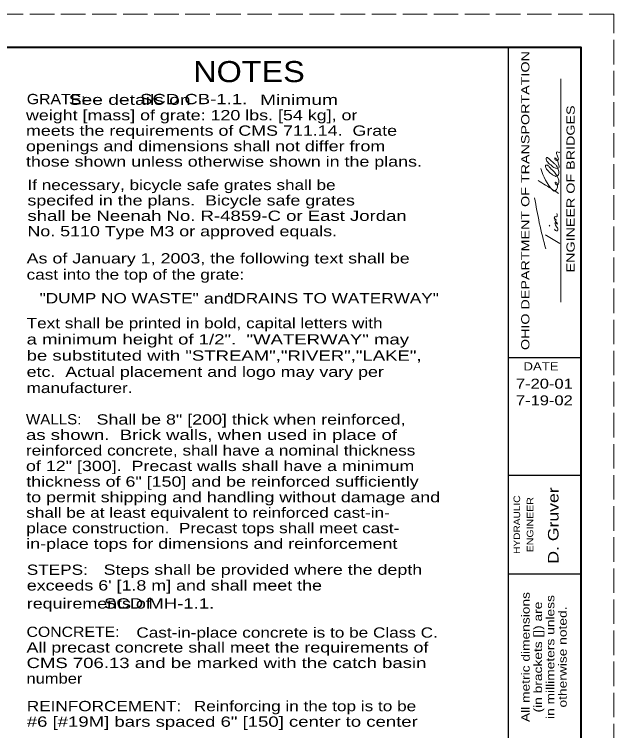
# Model space of a CAD drawing. Extents: x 1329.9 to 1363.9, y 715.5 to 737.5.
# Drawn here: x 1354.76 to 1363.86, y 726.62 to 737.5 of the extents above; entities that cross this region are included whole.
import ezdxf
from ezdxf.enums import TextEntityAlignment as Align

# ---------------------------------------------------------------- set-up
doc = ezdxf.new("R2010")
doc.units = 0
doc.header["$LTSCALE"] = 0.062
doc.linetypes.add('LONG_DASHED', pattern=[7.5, 6, -1.5])
doc.layers.add('1', color=7, linetype='Continuous', lineweight=13)

msp = doc.modelspace()

# ---------------------------------------------------------------- linework, layer by layer
at = {"layer": '1', "lineweight": 25}
for p, q in [((1331.86333, 736.9975), (1363.36333, 736.9975)), ((1362.26333, 715.9975), (1362.26333, 736.9975)), ((1363.36333, 736.9975), (1363.36333, 715.9975)), ((1363.36333, 732.28167), (1362.26333, 732.28167)), ((1363.36333, 730.4975), (1362.26333, 730.4975)), ((1363.36333, 728.9975), (1362.26333, 728.9975))]:
    msp.add_line(p, q, dxfattribs=at)
at = {"layer": '1'}
for p, q in [((1363.06208, 733.1285), (1363.06208, 736.51858)), ((1362.89458, 734.27942), (1362.88442, 734.29867))]:
    msp.add_line(p, q, dxfattribs=at)
at = {"layer": '1', "linetype": 'LONG_DASHED'}
msp.add_lwpolyline([(1329.86333, 715.4975), (1363.86333, 715.4975), (1363.86333, 737.4975), (1329.86333, 737.4975)], close=True, dxfattribs=at)
at = {"layer": '1', "lineweight": 40}
msp.add_lwpolyline([(1331.86333, 736.9975), (1363.36333, 736.9975), (1363.36333, 715.9975), (1331.86333, 715.9975)], close=True, dxfattribs=at)
msp.add_lwpolyline([(1331.86333, 736.9975), (1363.36333, 736.9975), (1363.36333, 715.9975), (1331.86333, 715.9975)], close=True, dxfattribs=at)
at = {"layer": '1'}
for points in [[(1362.75517, 735.1545), (1362.93833, 734.82617), (1362.9535, 734.81558), (1362.96367, 734.81558), (1362.99558, 734.83925), (1363.01067, 734.87342), (1363.00567, 734.92467), (1362.98875, 734.9465), (1362.97525, 734.9465), (1362.9735, 734.9335), (1362.98367, 734.91833), (1362.99717, 734.90992), (1363.01225, 734.90992), (1363.02742, 734.9315), (1363.03083, 734.95083), (1363.02058, 735.00617), (1362.93833, 735.12658), (1362.89283, 735.17125), (1362.85592, 735.20583), (1362.83075, 735.208), (1362.8325, 735.16942), (1362.85767, 735.13067), (1362.92492, 735.06833), (1362.967, 735.04292), (1363.00067, 735.03842), (1363.024, 735.06442), (1363.03083, 735.09858), (1363.02575, 735.12433), (1362.99558, 735.1975), (1362.96533, 735.2295), (1362.90475, 735.28292), (1362.87608, 735.30875), (1362.84258, 735.324), (1362.83917, 735.296), (1362.84925, 735.27017), (1362.90642, 735.21025), (1362.97708, 735.163), (1363.02908, 735.16533), (1363.02742, 735.223), (1363.01558, 735.26592), (1363.00225, 735.29167), (1362.99208, 735.30242), (1362.96867, 735.31742), (1362.97042, 735.30033), (1363.00567, 735.27883), (1363.02058, 735.28958), (1363.0075, 735.34325), (1362.99892, 735.37117), (1362.99558, 735.38383), (1362.99558, 735.39667), (1362.99558, 735.40533), (1363.02058, 735.40317), (1363.046, 735.40317)], [(1362.71633, 734.97225), (1362.94008, 734.83475), (1363.02575, 734.77908)], [(1362.83258, 733.93525), (1362.73392, 734.3305), (1362.66267, 734.71283)], [(1362.96367, 734.23417), (1362.97192, 734.2235), (1363.00908, 734.21058), (1363.01383, 734.243), (1362.98875, 734.27942), (1362.9735, 734.31567), (1362.9735, 734.33492), (1362.98875, 734.32867), (1362.99892, 734.31783), (1363.00908, 734.3135), (1362.98542, 734.34567), (1362.9735, 734.36067), (1362.97042, 734.378), (1362.99383, 734.37142), (1362.98542, 734.38008), (1362.96025, 734.40792), (1362.97042, 734.42308), (1362.98717, 734.42508), (1362.99558, 734.42308), (1363.00567, 734.44442), (1362.99892, 734.47233)], [(1363.04775, 734.01967), (1362.84258, 734.13967), (1362.827, 734.15008)]]:
    msp.add_spline(points, degree=3, dxfattribs=at)

# ---------------------------------------------------------------- texts
for s, height, width, p in [('OHIO DEPARTMENT OF TRANSPORTATION', 0.125, 1.3, (1362.58325, 734.66975)), ('ENGINEER OF BRIDGES', 0.125, 1.3, (1363.27158, 734.84654)), ('D. Gruver', 0.16, 1.25, (1363.02533, 729.73675)), ('HYDRAULIC', 0.1, 1.15, (1362.44242, 729.74858)), ('ENGINEER', 0.1, 1.2, (1362.64333, 729.74862)), ('All metric dimensions', 0.125, 1.25, (1362.58717, 727.73958)), ('in millimeters unless', 0.125, 1.25, (1362.96217, 727.73962)), ('(in brackets []) are', 0.125, 1.25, (1362.77467, 727.73958)), ('otherwise noted.', 0.125, 1.25, (1363.14967, 727.73958))]:
    msp.add_text(s, height=height, rotation=90, dxfattribs=dict(at, width=width)).set_placement(p, align=Align.CENTER)
for s, height, width, p in [('NOTES', 0.32, 1.15, (1357.47575, 736.468)), ('GRATE:', 0.156, 1.15, (1354.94825, 736.13333)), ('        See details on             Minimum', 0.156, 1.4, (1354.936, 736.12333)), ('                      SCD CB-1.1.', 0.156, 1.35, (1354.94825, 736.13333)), ('weight [mass] of grate: 120 lbs. [54 kg], or', 0.156, 1.3, (1354.936, 735.88867)), ('meets the requirements of CMS 711.14.  Grate', 0.156, 1.3, (1354.936, 735.654)), ('openings and dimensions shall not differ from', 0.156, 1.3, (1354.936, 735.41933)), ('those shown unless otherwise shown in the plans.', 0.156, 1.3, (1354.936, 735.18467)), ('If necessary, bicycle safe grates shall be', 0.156, 1.25, (1354.958, 734.82917)), ('specifed in the plans.  Bicycle safe grates', 0.156, 1.3, (1354.958, 734.59517)), ('shall be Neenah No. R-4859-C or East Jordan', 0.156, 1.35, (1354.958, 734.36117)), ('No. 5110 Type M3 or approved equals.', 0.156, 1.3, (1354.958, 734.12717)), ('As of January 1, 2003, the following text shall be ', 0.156, 1.3, (1354.94575, 733.71517)), ('cast into the top of the grate: ', 0.156, 1.25, (1354.94575, 733.46917)), ('   "DUMP NO WASTE"      "DRAINS TO WATERWAY"', 0.156, 1.25, (1354.92617, 733.10967)), (' and', 0.156, 1.3, (1357.563, 733.10708)), ('Text shall be printed in bold, capital letters with ', 0.156, 1.25, (1354.94575, 732.73117)), ('a minimum height of 1/2".  "WATERWAY" may ', 0.156, 1.35, (1354.94575, 732.48517)), ('be substituted with "STREAM","RIVER","LAKE", ', 0.156, 1.35, (1354.94575, 732.23917)), ('etc.  Actual placement and logo may vary per ', 0.156, 1.3, (1354.94575, 731.99317)), ('manufacturer.', 0.156, 1.25, (1354.94575, 731.74717)), ('WALLS:', 0.156, 1.1, (1354.936, 731.27133)), ('Shall be 8" [200] thick when reinforced,', 0.156, 1.3, (1356.00767, 731.26892)), ('as shown.  Brick walls, when used in place of ', 0.156, 1.35, (1354.936, 731.03525)), ('reinforced concrete, shall have a nominal thickness', 0.156, 1.25, (1354.936, 730.79917)), ('of 12" [300].  Precast walls shall have a minimum', 0.156, 1.3, (1354.936, 730.56308)), ('thickness of 6" [150] and be reinforced sufficiently', 0.156, 1.3, (1354.94008, 730.32533)), ('to permit shipping and handling without damage and', 0.156, 1.3, (1354.94008, 730.08925)), ('shall be at least equivalent to reinforced cast-in-', 0.156, 1.25, (1354.94008, 729.85358)), ('place construction.  Precast tops shall meet cast-', 0.156, 1.25, (1354.94008, 729.61892)), ('in-place tops for dimensions and reinforcement', 0.156, 1.3, (1354.94008, 729.38283)), ('STEPS:', 0.156, 1.25, (1354.94833, 728.98717)), ('Steps shall be provided where the depth', 0.156, 1.3, (1356.11533, 728.988)), ("exceeds 6' [1.8 m] and shall meet the", 0.156, 1.3, (1354.94833, 728.74967)), ('requirements of', 0.156, 1.3, (1354.94833, 728.47558)), ('               SCD MH-1.1.', 0.156, 1.35, (1354.94833, 728.47558)), ('CONCRETE:', 0.156, 1.15, (1354.94425, 728.04433)), ('Cast-in-place concrete is to be Class C.', 0.156, 1.25, (1356.6125, 728.0335)), ('All precast concrete shall meet the requirements of', 0.156, 1.3, (1354.94425, 727.80825)), ('CMS 706.13 and be marked with the catch basin', 0.156, 1.35, (1354.94425, 727.57217)), ('number', 0.156, 1.2, (1354.94425, 727.33608)), ('REINFORCEMENT:', 0.156, 1.25, (1354.94833, 726.91708)), ('Reinforcing in the top is to be', 0.156, 1.25, (1357.48575, 726.91708)), ('#6 [#19M] bars spaced 6" [150] center to center', 0.156, 1.35, (1354.94833, 726.68092))]:
    msp.add_text(s, height=height, dxfattribs=dict(at, width=width)).set_placement(p)
for s, height, width, p in [('DATE', 0.125, 1.2, (1362.76004, 732.09025)), ('7-20-01', 0.15, 1.25, (1362.81038, 731.81475)), ('7-19-02', 0.15, 1.25, (1362.81038, 731.56167))]:
    msp.add_text(s, height=height, dxfattribs=dict(at, width=width)).set_placement(p, align=Align.CENTER)

doc.saveas('drawing.dxf')
